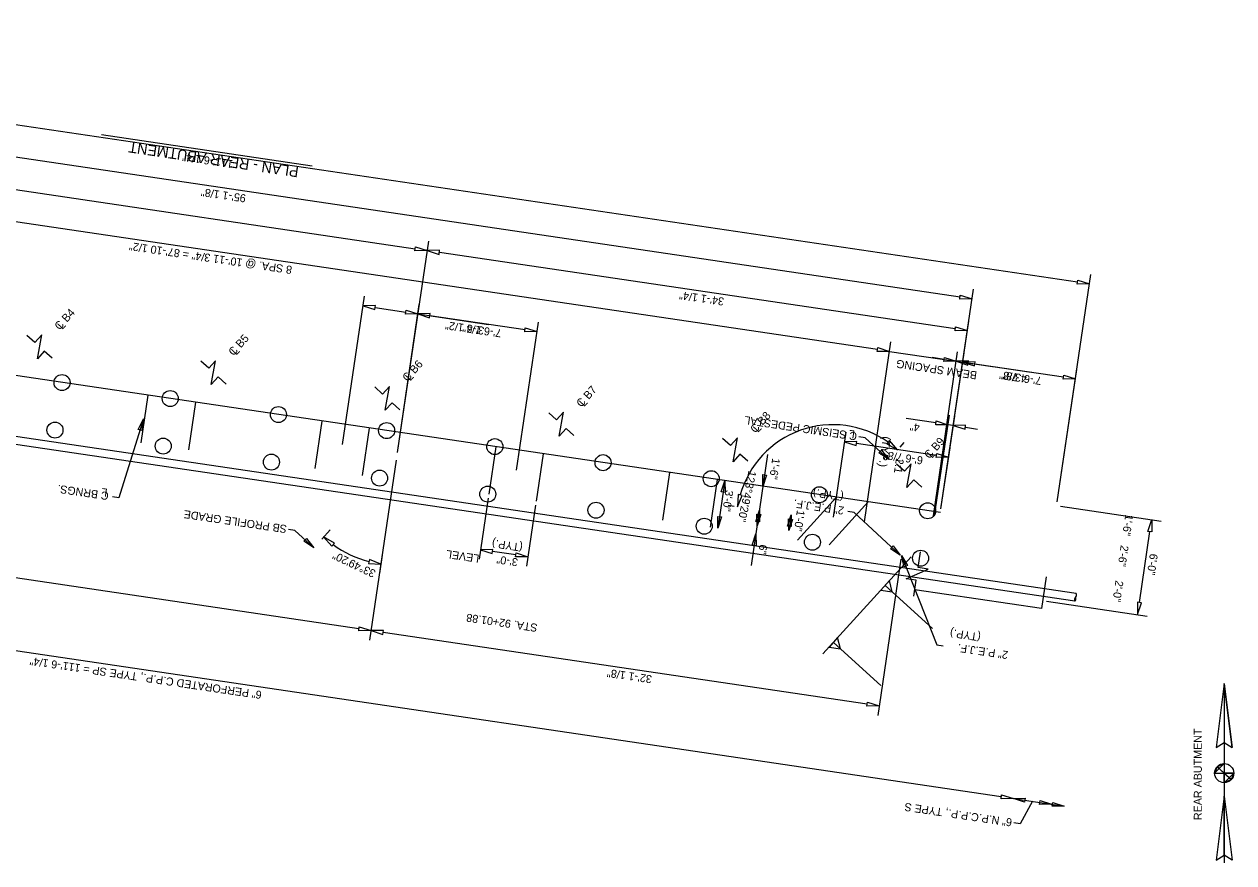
# Model space of a CAD drawing. Extents: x 1468952 to 1469933, y 573916 to 574220.
# Drawn here: x 1469009.2 to 1469084.8, y 573991.1 to 574043.5 of the extents above; entities that cross this region are included whole.
import ezdxf

# ---------------------------------------------------------------- set-up
doc = ezdxf.new("R2010")
doc.units = 0
for name, color, linetype in [('BR_P_Beam_Object', 7, 'Continuous'), ('BR_P_Gen_Centerline', 7, 'Continuous'), ('BR_P_Sub_Centerline', 7, 'Continuous'), ('BR_P_Sub_Deep_Centerline', 7, 'Continuous'), ('BR_X_SV_Beam_Seat', 7, 'Continuous'), ('Default', 7, 'Continuous'), ('SV_X_Text_Elevation', 7, 'Continuous')]:
    doc.layers.add(name, color=color, linetype=linetype)

# ---------------------------------------------------------------- blocks, each defined once
blk = doc.blocks.new('arrowOhio')
at = {"layer": 'Default'}
blk.add_lwpolyline([(0.00381, 0.000635), (0.00381, -0.000635), (0, 0)], close=True, dxfattribs=at)
blk = doc.blocks.new('north')
at = {"layer": 'Default'}
for p, q in [((0.02961, 0.00001), (-0.02965, 0.00001)), ((-0.00766, 0.00001), (-0.02883, 0.00266)), ((-0.02883, -0.00263), (-0.02712, 0.00001)), ((-0.00766, 0.00001), (-0.02883, -0.00263)), ((-0.00002, 0.00319), (-0.00002, -0.00316)), ((0.00845, 0.00266), (0.01016, 0.00001)), ((0.02961, 0.00001), (0.00845, 0.00266)), ((0.02961, 0.00001), (0.00845, -0.00263))]:
    blk.add_line(p, q, dxfattribs=at)
for points in [[(-0.00766, 0.00001), (-0.02883, 0.00266), (-0.02712, 0.00001)], [(-0.00214, -0.00235), (-0.00278, -0.00156), (-0.0032, 0.00001)], [(-0.00002, 0.00001), (-0.00152, -0.00166), (-0.0032, 0.00001)], [(-0.00002, -0.00316), (-0.00002, 0.00001), (-0.00214, -0.00235), (-0.0032, 0.00001)], [(-0.00002, 0.00319), (-0.00002, 0.00001), (0.0021, 0.00238), (0.00315, 0.00001)], [(-0.00002, 0.00319), (0.00148, 0.00169), (0.0021, 0.00238)], [(-0.00002, 0.00319), (0.0021, 0.00238), (0.0011, 0.00298)], [(-0.00002, 0.00001), (0.00148, 0.00169), (0.00315, 0.00001)], [(0.0021, 0.00238), (0.00274, 0.00158), (0.00315, 0.00001)], [(0.02961, 0.00001), (0.01016, 0.00001), (0.00845, -0.00263)], [(-0.00002, -0.00316), (-0.00152, -0.00166), (-0.00214, -0.00235)], [(-0.00002, -0.00316), (-0.00214, -0.00235), (-0.00114, -0.00296)]]:
    blk.add_lwpolyline(points, close=True, dxfattribs=at)
blk.add_circle((-0.00002, 0.00001), 0.00317, dxfattribs=at)

msp = doc.modelspace()

# ---------------------------------------------------------------- linework, layer by layer
at = {"layer": 'BR_P_Beam_Object'}
for p, q in [((1469057.531, 574011.304), (1469059.959, 574013.977)), ((1469059.509, 574011.011), (1469061.937, 574013.684))]:
    msp.add_line(p, q, dxfattribs=at)
at = {"layer": 'BR_P_Gen_Centerline'}
for p, q in [((1469074.927, 574007.97), (1468960.648, 574024.889)), ((1469074.854, 574007.475), (1468960.574, 574024.394))]:
    msp.add_line(p, q, dxfattribs=at)
for centre, start, end in [((1469075.002, 574007.58), 127.97595, 215.18159), ((1469074.743, 574007.618), 307.97595, 35.18159), ((1469074.779, 574007.866), 307.97595, 35.18159)]:
    msp.add_arc(centre, 0.181, start, end, dxfattribs=at)
at = {"layer": 'BR_P_Sub_Centerline'}
for centre in [(1469011.577, 574021.14), (1469018.337, 574020.139), (1469025.096, 574019.138), (1469011.138, 574018.172), (1469031.856, 574018.137), (1469017.897, 574017.171), (1469038.616, 574017.137), (1469024.657, 574016.171), (1469045.375, 574016.136), (1469031.417, 574015.17), (1469052.135, 574015.135), (1469038.176, 574014.169), (1469058.895, 574014.134), (1469044.936, 574013.168), (1469065.654, 574013.134), (1469051.696, 574012.168), (1469058.455, 574011.167), (1469065.215, 574010.166)]:
    msp.add_circle(centre, 0.5, dxfattribs=at)
at = {"layer": 'BR_P_Sub_Deep_Centerline'}
for p, q in [((1469066.452, 574013.016), (1468972.385, 574026.942)), ((1469016.94, 574020.346), (1469016.501, 574017.378)), ((1469019.908, 574019.906), (1469019.469, 574016.939)), ((1469027.806, 574018.737), (1469027.366, 574015.769)), ((1469030.773, 574018.298), (1469030.334, 574015.33)), ((1469038.671, 574017.129), (1469038.232, 574014.161)), ((1469041.639, 574016.689), (1469041.199, 574013.722)), ((1469049.536, 574015.52), (1469049.097, 574012.552)), ((1469052.504, 574015.081), (1469052.065, 574012.113))]:
    msp.add_line(p, q, dxfattribs=at)
at = {"layer": 'BR_X_SV_Beam_Seat'}
for p, q in [((1469062.525, 574023.201), (1468977.106, 574035.847)), ((1469061.701, 574012.445), (1469063.365, 574023.683)), ((1469063.277, 574023.089), (1469069.707, 574022.137)), ((1469055.657, 574016.636), (1469055.027, 574012.382)), ((1469052.99, 574015.009), (1469052.551, 574012.041)), ((1469055.115, 574012.976), (1469054.632, 574009.711)), ((1469057.123, 574012.88), (1469056.976, 574011.891)), ((1469070.257, 573995.267), (1468961.437, 574011.377)), ((1469064.62, 574010.254), (1469059.117, 574004.195)), ((1469073.059, 574009.005), (1469072.766, 574007.026)), ((1469063.001, 574008.472), (1469065.962, 574005.783)), ((1469072.766, 574007.026), (1469064.852, 574008.198)), ((1469059.764, 574004.908), (1469062.725, 574002.219)), ((1469071.009, 573995.156), (1469074.174, 573994.687)), ((1469072.196, 573994.98), (1469071.434, 573993.573)), ((1469071.434, 573993.573), (1469071.038, 573993.632))]:
    msp.add_line(p, q, dxfattribs=at)
for points in [[(1469062.506, 574023.075), (1469062.544, 574023.326), (1469063.277, 574023.089)], [(1469062.732, 574008.176), (1469063.445, 574008.069), (1469063.27, 574008.768)], [(1469059.495, 574004.612), (1469060.208, 574004.504), (1469060.033, 574005.204)], [(1469070.238, 573995.142), (1469070.275, 573995.392), (1469071.009, 573995.156)]]:
    msp.add_lwpolyline(points, close=True, dxfattribs=at)
at = {"layer": 'SV_X_Text_Elevation'}
for p, q in [((1469075.016, 574027.417), (1468966.197, 574043.527)), ((1469067.677, 574026.481), (1468975.114, 574040.185)), ((1468974.821, 574038.207), (1469033.645, 574029.498)), ((1469027.209, 574034.662), (1469014.053, 574036.61)), ((1469032.528, 574016.764), (1469034.485, 574029.98)), ((1469032.528, 574016.764), (1469034.485, 574029.98)), ((1469067.384, 574024.503), (1469035.149, 574029.275)), ((1469073.753, 574013.694), (1469075.856, 574027.899)), ((1469066.487, 574013.253), (1469068.517, 574026.964)), ((1469029.105, 574017.271), (1469030.476, 574026.53)), ((1469031.14, 574025.825), (1469033.059, 574025.541)), ((1469032.528, 574016.764), (1469033.899, 574026.023)), ((1469032.528, 574016.764), (1469033.899, 574026.023)), ((1469033.811, 574025.43), (1469038.226, 574024.776)), ((1469040.501, 574024.439), (1469034.563, 574025.318)), ((1469039.97, 574015.662), (1469041.341, 574024.921)), ((1469066.487, 574013.253), (1469068.224, 574024.985)), ((1469066.688, 574022.584), (1469065.936, 574022.696)), ((1469066.01, 574012.818), (1469067.527, 574023.067)), ((1469066.303, 574014.797), (1469067.527, 574023.067)), ((1469066.487, 574013.253), (1469067.931, 574023.007)), ((1469067.439, 574022.473), (1469067.843, 574022.413)), ((1469074.138, 574021.481), (1469068.191, 574022.362)), ((1469068.595, 574022.302), (1469072.126, 574021.779)), ((1469073.753, 574013.694), (1469074.977, 574021.964)), ((1469016.666, 574018.87), (1469015.127, 574013.942)), ((1469066.174, 574018.617), (1469064.313, 574018.892)), ((1469066.082, 574012.808), (1469067.014, 574019.099)), ((1469066.487, 574013.253), (1469067.345, 574019.05)), ((1469059.769, 574012.731), (1469060.554, 574018.033)), ((1469067.257, 574018.456), (1469066.926, 574018.505)), ((1469068.009, 574018.345), (1469068.761, 574018.234)), ((1469066.213, 574016.589), (1469061.218, 574017.329)), ((1469061.749, 574017.688), (1469061.354, 574017.747)), ((1469063.23, 574016.343), (1469061.749, 574017.688)), ((1469063.929, 574017.113), (1469064.18, 574017.39)), ((1469066.487, 574013.253), (1469067.052, 574017.071)), ((1469032.458, 574016.289), (1469030.794, 574005.052)), ((1469032.458, 574016.289), (1469030.794, 574005.052)), ((1469030.13, 574005.757), (1468969.318, 574014.76)), ((1469015.127, 574013.942), (1469014.732, 574014.001)), ((1469038.196, 574013.923), (1469037.631, 574010.105)), ((1469041.164, 574013.484), (1469040.599, 574009.666)), ((1469053.561, 574013.408), (1469053.192, 574013.462)), ((1469073.955, 574013.421), (1469080.247, 574012.49)), ((1469061.063, 574013.032), (1469060.667, 574013.09)), ((1469063.942, 574010.355), (1469061.063, 574013.032)), ((1469026.13, 574011.899), (1469025.734, 574011.958)), ((1469027.314, 574010.824), (1469026.13, 574011.899)), ((1469027.799, 574011.358), (1469028.325, 574011.937)), ((1469078.886, 574007.394), (1469079.542, 574011.826)), ((1469031.579, 574010.354), (1469031.409, 574009.207)), ((1469039.935, 574010.371), (1469038.471, 574010.587)), ((1469064.024, 574010.342), (1469066.231, 574004.763)), ((1469063.989, 574010.105), (1469062.545, 574000.351)), ((1469063.989, 574010.105), (1469062.545, 574000.351)), ((1469073.077, 574007.486), (1469079.368, 574006.554)), ((1469061.881, 574001.056), (1469031.634, 574005.534)), ((1469066.231, 574004.763), (1469066.627, 574004.704))]:
    msp.add_line(p, q, dxfattribs=at)
for points in [[(1469033.627, 574029.373), (1469033.664, 574029.623), (1469034.397, 574029.387)], [(1469035.13, 574029.15), (1469035.167, 574029.401), (1469034.397, 574029.387)], [(1469074.998, 574027.291), (1469075.035, 574027.542), (1469075.768, 574027.305)], [(1469067.659, 574026.356), (1469067.696, 574026.607), (1469068.429, 574026.37)], [(1469031.121, 574025.7), (1469031.158, 574025.951), (1469030.388, 574025.937)], [(1469033.041, 574025.416), (1469033.078, 574025.666), (1469033.811, 574025.43)], [(1469034.544, 574025.193), (1469034.582, 574025.444), (1469033.811, 574025.43)], [(1469040.483, 574024.314), (1469040.52, 574024.565), (1469041.253, 574024.328)], [(1469067.366, 574024.378), (1469067.403, 574024.628), (1469068.136, 574024.392)], [(1469066.669, 574022.459), (1469066.706, 574022.71), (1469067.439, 574022.473)], [(1469068.173, 574022.236), (1469068.21, 574022.487), (1469067.439, 574022.473)], [(1469068.576, 574022.177), (1469068.614, 574022.427), (1469067.843, 574022.413)], [(1469074.119, 574021.356), (1469074.156, 574021.607), (1469074.889, 574021.37)], [(1469066.156, 574018.491), (1469066.193, 574018.742), (1469066.926, 574018.505)], [(1469067.991, 574018.22), (1469068.028, 574018.47), (1469067.257, 574018.456)], [(1469061.199, 574017.203), (1469061.237, 574017.454), (1469060.466, 574017.44)], [(1469063.262, 574017.519), (1469063.104, 574017.321), (1469063.777, 574016.946)], [(1469066.194, 574016.464), (1469066.231, 574016.715), (1469066.964, 574016.478)], [(1469054.068, 574014.091), (1469053.82, 574014.144), (1469053.785, 574013.375)], [(1469079.667, 574011.807), (1469079.417, 574011.844), (1469079.653, 574012.578)], [(1469028.432, 574010.916), (1469028.592, 574011.112), (1469027.922, 574011.493)], [(1469038.452, 574010.462), (1469038.489, 574010.713), (1469037.719, 574010.699)], [(1469039.916, 574010.245), (1469039.953, 574010.496), (1469040.687, 574010.259)], [(1469030.778, 574010.077), (1469030.727, 574009.829), (1469031.497, 574009.8)], [(1469079.011, 574007.376), (1469078.76, 574007.413), (1469078.774, 574006.642)], [(1469030.112, 574005.631), (1469030.149, 574005.882), (1469030.882, 574005.645)], [(1469031.615, 574005.409), (1469031.653, 574005.659), (1469030.882, 574005.645)], [(1469061.863, 574000.931), (1469061.9, 574001.181), (1469062.633, 574000.945)]]:
    msp.add_lwpolyline(points, close=True, dxfattribs=at)
for points in [[(1469010.957, 574022.656), (1469010.467, 574023.101), (1469010.037, 574022.627), (1469010.306, 574024.112), (1469009.875, 574023.638), (1469009.386, 574024.083)], [(1469021.823, 574021.047), (1469021.333, 574021.492), (1469020.903, 574021.018), (1469021.171, 574022.504), (1469020.741, 574022.03), (1469020.251, 574022.475)], [(1469032.688, 574019.439), (1469032.198, 574019.884), (1469031.768, 574019.41), (1469032.036, 574020.895), (1469031.606, 574020.421), (1469031.116, 574020.866)], [(1469043.553, 574017.83), (1469043.064, 574018.275), (1469042.633, 574017.801), (1469042.902, 574019.287), (1469042.471, 574018.813), (1469041.982, 574019.257)], [(1469054.419, 574016.222), (1469053.929, 574016.666), (1469053.499, 574016.193), (1469053.767, 574017.678), (1469053.337, 574017.204), (1469052.847, 574017.649)], [(1469065.284, 574014.613), (1469064.794, 574015.058), (1469064.364, 574014.584), (1469064.632, 574016.069), (1469064.202, 574015.596), (1469063.712, 574016.04)], [(1469064.794, 574007.802), (1469064.94, 574008.792), (1469064.307, 574008.885), (1469065.69, 574009.489), (1469065.057, 574009.583), (1469065.204, 574010.572)]]:
    msp.add_lwpolyline(points, dxfattribs=at)
for centre, radius, start, end in [((1469059.734, 574012.494), 6.013, 55.00277, 164.33255), ((1469032.493, 574016.527), 6.8, 234.16353, 255.17179)]:
    msp.add_arc(centre, radius, start, end, dxfattribs=at)

# ---------------------------------------------------------------- block references
at = {"layer": 'BR_X_SV_Beam_Seat'}
for name, p, xscale, yscale, rotation in [('arrowOhio', (1469052.99, 574015.009), 191.49568000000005, 191.49568, -98.42123067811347), ('arrowOhio', (1469055.364, 574014.657), 191.49568000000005, 191.49568, 81.57876932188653), ('arrowOhio', (1469052.551, 574012.041), 191.49568000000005, 191.49568, 81.57876932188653), ('arrowOhio', (1469054.998, 574012.184), 191.49568000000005, 191.49568, 81.57876932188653), ('arrowOhio', (1469055.144, 574013.173), 191.49568000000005, 191.49568, -98.42123067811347), ('arrowOhio', (1469056.976, 574011.891), 191.49568000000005, 191.49568, 81.57876932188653), ('arrowOhio', (1469057.123, 574012.88), 191.49568000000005, 191.49568, -98.42123067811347), ('arrowOhio', (1469054.925, 574011.69), 191.49568000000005, 191.49568, -98.42123067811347), ('north', (1469084.183, 573996.744), 188.97600000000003, 188.976, 90.00015820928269), ('arrowOhio', (1469071.009, 573995.156), 191.49568000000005, 191.49568, -8.421230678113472), ('arrowOhio', (1469073.383, 573994.804), 191.49568000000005, 191.49568, 171.57876932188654), ('arrowOhio', (1469074.174, 573994.687), 191.49568000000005, 191.49568, 171.57876932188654)]:
    msp.add_blockref(name, p, dxfattribs=dict(at, xscale=xscale, yscale=yscale, rotation=rotation))
at = {"layer": 'SV_X_Text_Elevation'}
for p, xscale, yscale, rotation in [((1469016.666, 574018.87), 191.49568000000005, 191.49568, -107.33615763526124), ((1469063.23, 574016.343), 191.49568000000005, 191.49568, 137.75654709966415), ((1469027.314, 574010.824), 191.49568, 191.49568, 137.75654709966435), ((1469063.942, 574010.355), 191.49568000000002, 191.49567999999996, 137.08046284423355), ((1469064.024, 574010.342), 191.49568, 191.49568, -68.42123067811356)]:
    msp.add_blockref('arrowOhio', p, dxfattribs=dict(at, xscale=xscale, yscale=yscale, rotation=rotation))

# ---------------------------------------------------------------- texts
at = {"layer": 'BR_X_SV_Beam_Seat'}
for s, p in [('8 SPA. @ 10\'-11 3/4" = 87\'-10 1/2"', (1469025.976, 574028.409)), ('6" PERFORATED C.P.P., TYPE SP = 111\'-6 1/4"', (1469024.079, 574001.86))]:
    msp.add_text(s, height=0.5, rotation=171.57877, dxfattribs=at).set_placement(p)
at = {"layer": 'SV_X_Text_Elevation'}
for s, height, rotation, p in [('PLAN - REAR ABUTMENT', 0.665, 171.57877, (1469026.398, 574034.614)), ('111\'-6 1/4"', 0.5, 171.57877, (1469022.293, 574035.02)), ('95\'-1 1/8"', 0.5, 171.57877, (1469023.09, 574032.88)), ('34\'-1 1/4"', 0.5, 171.57877, (1469052.968, 574026.435)), ('C B4', 0.5, 47.75655, (1469011.427, 574024.38)), ('L', 0.5, 47.75655, (1469011.602, 574024.424)), ('3\'-5 1/2"', 0.5, 171.57877, (1469037.979, 574024.611)), ('7\'-6 1/4"', 0.5, 171.57877, (1469039.059, 574024.451)), ('C B5', 0.5, 47.75655, (1469022.292, 574022.772)), ('L', 0.5, 47.75655, (1469022.467, 574022.816)), ('C B6', 0.5, 47.75655, (1469033.158, 574021.163)), ('BEAM SPACING', 0.5, 171.57877, (1469068.764, 574021.826)), ('L', 0.5, 47.75655, (1469033.333, 574021.207)), ('4 7/8"', 0.5, 171.57877, (1469071.883, 574021.613)), ('7\'-6 3/8"', 0.5, 171.57877, (1469072.794, 574021.478)), ('C B7', 0.5, 47.75655, (1469044.023, 574019.555)), ('L', 0.5, 47.75655, (1469044.198, 574019.599)), ('C SEISMIC PEDESTAL', 0.5, 171.57877, (1469061.271, 574018.011)), ('C B8', 0.5, 47.75655, (1469054.889, 574017.946)), ('4"', 0.5, 171.57877, (1469065.188, 574018.56)), ('L', 0.5, 47.75655, (1469055.063, 574017.99)), ('L', 0.5, 171.57877, (1469061.138, 574018.132)), ('(TYP.)', 0.5, 261.57877, (1469062.874, 574017.806)), ('C B9', 0.5, 47.75655, (1469065.754, 574016.338)), ('1\'-6"', 0.5, 261.57877, (1469055.952, 574016.443)), ('6\'-6 7/8"', 0.5, 171.57877, (1469065.391, 574016.509)), ('2:1', 0.5, 261.57877, (1469063.681, 574016.427)), ('L', 0.5, 47.75655, (1469065.929, 574016.381)), ('123°49\'20"', 0.5, 257.76469, (1469054.473, 574015.665)), ('C BRNGS.', 0.5, 171.57877, (1469014.521, 574014.285)), ('L', 0.5, 171.57877, (1469014.442, 574014.499)), ('3\'-0"', 0.5, 261.57877, (1469053.028, 574014.444)), ('(TYP.)', 0.5, 171.57877, (1469060.433, 574014.237)), ('2" P.E.J.F.', 0.5, 171.57877, (1469060.457, 574013.374)), ('SB PROFILE GRADE ', 0.5, 171.57877, (1469025.652, 574012.223)), ('1\'-0"', 0.5, 261.57877, (1469057.494, 574013.203)), ('1\'-6"', 0.5, 261.57877, (1469078.006, 574012.925)), ('(TYP.)', 0.5, 171.57877, (1469040.384, 574011.066)), ('33°49\'20"', 0.5, 154.66766, (1469031.222, 574009.384)), ('LEVEL', 0.5, 171.57877, (1469037.671, 574010.376)), ('3\'-0"', 0.5, 171.57877, (1469040.083, 574010.146)), ('6"', 0.5, 261.57877, (1469055.154, 574011.051)), ('2\'-6"', 0.5, 261.57877, (1469077.722, 574011.003)), ('6\'-0"', 0.5, 261.57877, (1469079.545, 574010.479)), ('2\'-0"', 0.5, 261.57877, (1469077.395, 574008.798)), ('STA. 92+01.88', 0.5, 171.57877, (1469041.308, 574006.052)), ('(TYP.)', 0.5, 171.57877, (1469068.998, 574005.465)), ('2" P.E.J.F.', 0.5, 171.57877, (1469070.705, 574004.353)), ('32\'-1 1/8"', 0.5, 171.57877, (1469048.456, 574002.842)), ('REAR ABUTMENT', 0.5, 90.00016, (1469082.783, 573993.809)), ('6" N.P.C.P.P., TYPE S', 0.5, 171.57877, (1469070.956, 573993.896))]:
    msp.add_text(s, height=height, rotation=rotation, dxfattribs=at).set_placement(p)

doc.saveas('drawing.dxf')
